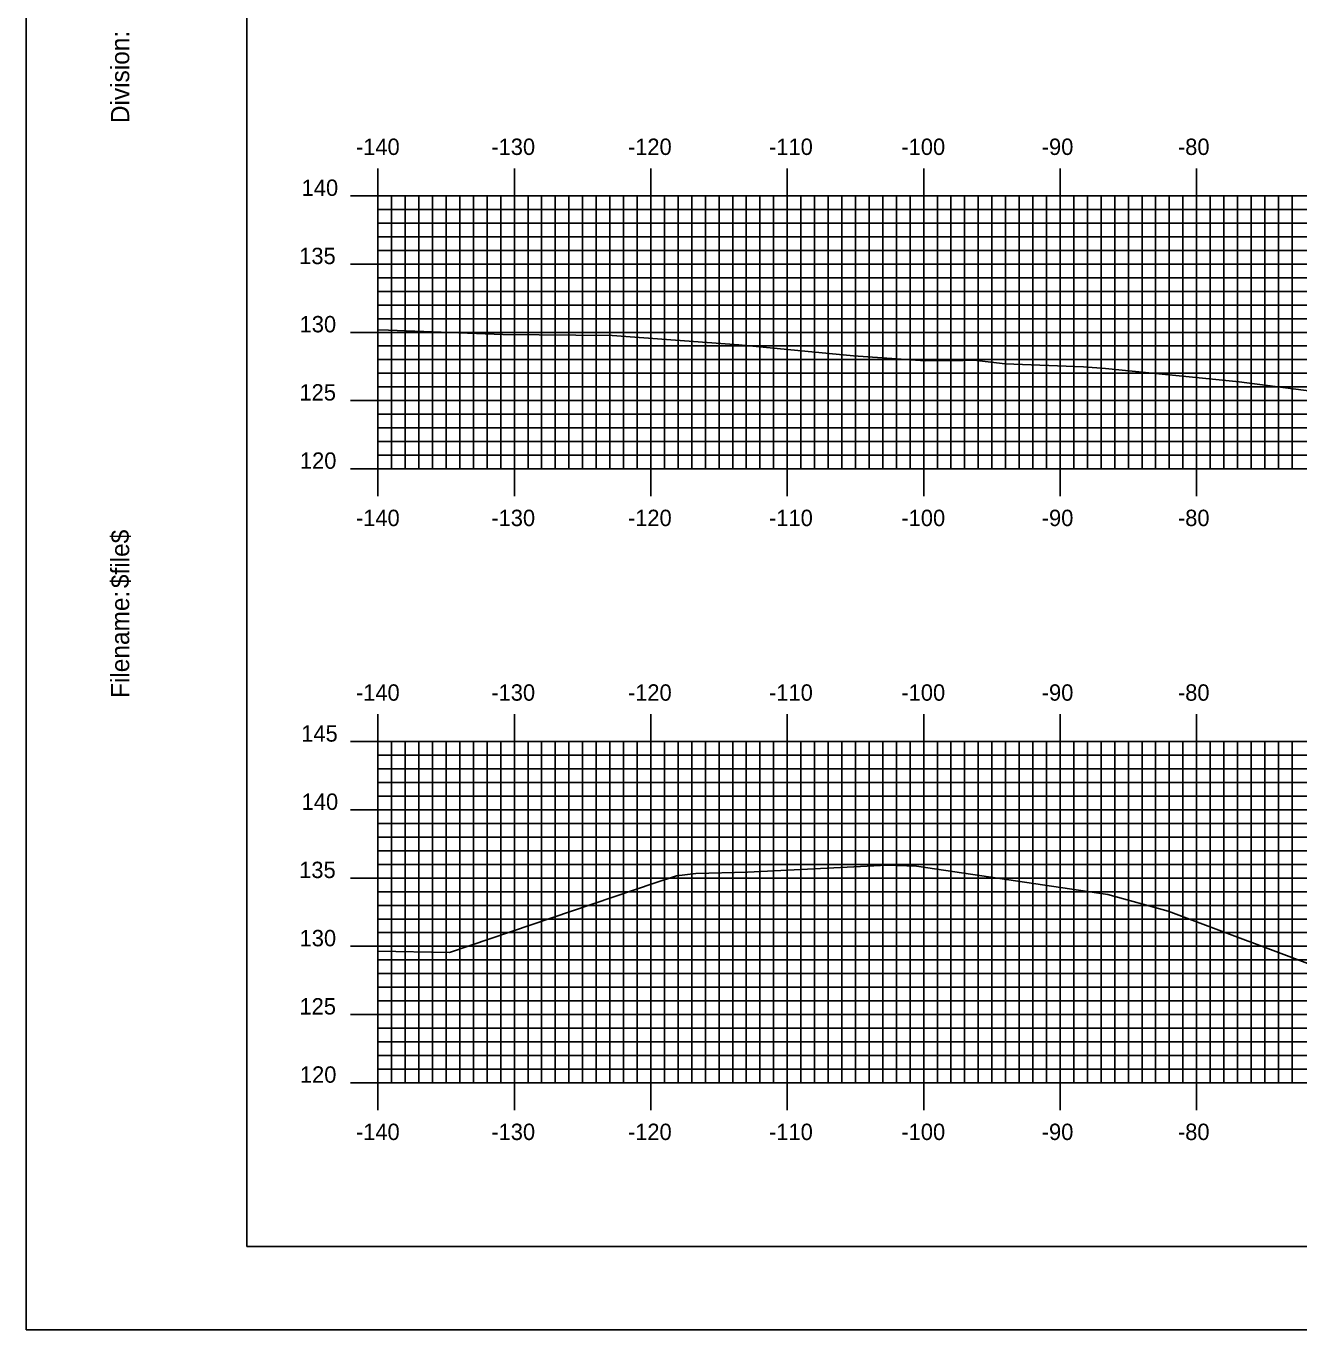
# Model space of a CAD drawing. Extents: x 850746 to 851089, y 366605 to 366825.
# Drawn here: x 850745.6 to 850838.9, y 366604.9 to 366700.5 of the extents above; entities that cross this region are included whole.
import ezdxf

# ---------------------------------------------------------------- set-up
doc = ezdxf.new("R2010")
doc.units = 0
for name, color, linetype in [('BORDER', 7, 'Continuous'), ('H_V ANNOTATION', 7, 'Continuous'), ('MAJOR', 7, 'Continuous'), ('MINOR', 7, 'Continuous'), ('PLOT BOUNDARY', 7, 'Continuous'), ('S_Roadway_Centerline', 7, 'Continuous')]:
    doc.layers.add(name, color=color, linetype=linetype)

msp = doc.modelspace()

# ---------------------------------------------------------------- linework, layer by layer
at = {"layer": 'BORDER'}
msp.add_lwpolyline([(850761.825, 366611.055), (851081.825, 366611.055), (851081.825, 366821.055), (850761.825, 366821.055)], close=True, dxfattribs=at)
at = {"layer": 'MAJOR'}
for p, q in [((850771.425, 366690.059), (850771.425, 366688.055)), ((850781.425, 366690.059), (850781.425, 366688.055)), ((850791.425, 366690.059), (850791.425, 366688.055)), ((850801.425, 366690.059), (850801.425, 366688.055)), ((850811.425, 366690.059), (850811.425, 366688.055)), ((850821.425, 366690.059), (850821.425, 366688.055)), ((850831.425, 366690.059), (850831.425, 366688.055)), ((850769.421, 366688.055), (850771.425, 366688.055)), ((850771.425, 366688.055), (851051.425, 366688.055)), ((850771.425, 366668.055), (850771.425, 366688.055)), ((850771.425, 366668.055), (850771.425, 366688.055)), ((850771.425, 366688.055), (851051.425, 366688.055)), ((850781.425, 366668.055), (850781.425, 366688.055)), ((850791.425, 366668.055), (850791.425, 366688.055)), ((850801.425, 366668.055), (850801.425, 366688.055)), ((850811.425, 366668.055), (850811.425, 366688.055)), ((850821.425, 366668.055), (850821.425, 366688.055)), ((850831.425, 366668.055), (850831.425, 366688.055)), ((850769.421, 366683.055), (850771.425, 366683.055)), ((850771.425, 366683.055), (851051.425, 366683.055)), ((850769.421, 366678.055), (850771.425, 366678.055)), ((850771.425, 366678.055), (851051.425, 366678.055)), ((850769.421, 366673.055), (850771.425, 366673.055)), ((850771.425, 366673.055), (851051.425, 366673.055)), ((850769.421, 366668.055), (850771.425, 366668.055)), ((850771.425, 366668.055), (851051.425, 366668.055)), ((850771.425, 366668.055), (851051.425, 366668.055)), ((850771.425, 366666.051), (850771.425, 366668.055)), ((850781.425, 366666.051), (850781.425, 366668.055)), ((850791.425, 366666.051), (850791.425, 366668.055)), ((850801.425, 366666.051), (850801.425, 366668.055)), ((850811.425, 366666.051), (850811.425, 366668.055)), ((850821.425, 366666.051), (850821.425, 366668.055)), ((850831.425, 366666.051), (850831.425, 366668.055)), ((850771.425, 366650.059), (850771.425, 366648.055)), ((850781.425, 366650.059), (850781.425, 366648.055)), ((850791.425, 366650.059), (850791.425, 366648.055)), ((850801.425, 366650.059), (850801.425, 366648.055)), ((850811.425, 366650.059), (850811.425, 366648.055)), ((850821.425, 366650.059), (850821.425, 366648.055)), ((850831.425, 366650.059), (850831.425, 366648.055)), ((850769.421, 366648.055), (850771.425, 366648.055)), ((850771.425, 366648.055), (851051.425, 366648.055)), ((850771.425, 366623.055), (850771.425, 366648.055)), ((850771.425, 366623.055), (850771.425, 366648.055)), ((850771.425, 366648.055), (851051.425, 366648.055)), ((850781.425, 366623.055), (850781.425, 366648.055)), ((850791.425, 366623.055), (850791.425, 366648.055)), ((850801.425, 366623.055), (850801.425, 366648.055)), ((850811.425, 366623.055), (850811.425, 366648.055)), ((850821.425, 366623.055), (850821.425, 366648.055)), ((850831.425, 366623.055), (850831.425, 366648.055)), ((850769.421, 366643.055), (850771.425, 366643.055)), ((850771.425, 366643.055), (851051.425, 366643.055)), ((850769.421, 366638.055), (850771.425, 366638.055)), ((850771.425, 366638.055), (851051.425, 366638.055)), ((850769.421, 366633.055), (850771.425, 366633.055)), ((850771.425, 366633.055), (851051.425, 366633.055)), ((850769.421, 366628.055), (850771.425, 366628.055)), ((850771.425, 366628.055), (851051.425, 366628.055)), ((850769.421, 366623.055), (850771.425, 366623.055)), ((850771.425, 366623.055), (851051.425, 366623.055)), ((850771.425, 366623.055), (851051.425, 366623.055)), ((850771.425, 366621.051), (850771.425, 366623.055)), ((850781.425, 366621.051), (850781.425, 366623.055)), ((850791.425, 366621.051), (850791.425, 366623.055)), ((850801.425, 366621.051), (850801.425, 366623.055)), ((850811.425, 366621.051), (850811.425, 366623.055)), ((850821.425, 366621.051), (850821.425, 366623.055)), ((850831.425, 366621.051), (850831.425, 366623.055))]:
    msp.add_line(p, q, dxfattribs=at)
at = {"layer": 'MINOR'}
for p, q in [((850772.425, 366668.055), (850772.425, 366688.055)), ((850773.425, 366668.055), (850773.425, 366688.055)), ((850774.425, 366668.055), (850774.425, 366688.055)), ((850775.425, 366668.055), (850775.425, 366688.055)), ((850776.425, 366668.055), (850776.425, 366688.055)), ((850777.425, 366668.055), (850777.425, 366688.055)), ((850778.425, 366668.055), (850778.425, 366688.055)), ((850779.425, 366668.055), (850779.425, 366688.055)), ((850780.425, 366668.055), (850780.425, 366688.055)), ((850782.425, 366668.055), (850782.425, 366688.055)), ((850783.425, 366668.055), (850783.425, 366688.055)), ((850784.425, 366668.055), (850784.425, 366688.055)), ((850785.425, 366668.055), (850785.425, 366688.055)), ((850786.425, 366668.055), (850786.425, 366688.055)), ((850787.425, 366668.055), (850787.425, 366688.055)), ((850788.425, 366668.055), (850788.425, 366688.055)), ((850789.425, 366668.055), (850789.425, 366688.055)), ((850790.425, 366668.055), (850790.425, 366688.055)), ((850792.425, 366668.055), (850792.425, 366688.055)), ((850793.425, 366668.055), (850793.425, 366688.055)), ((850794.425, 366668.055), (850794.425, 366688.055)), ((850795.425, 366668.055), (850795.425, 366688.055)), ((850796.425, 366668.055), (850796.425, 366688.055)), ((850797.425, 366668.055), (850797.425, 366688.055)), ((850798.425, 366668.055), (850798.425, 366688.055)), ((850799.425, 366668.055), (850799.425, 366688.055)), ((850800.425, 366668.055), (850800.425, 366688.055)), ((850802.425, 366668.055), (850802.425, 366688.055)), ((850803.425, 366668.055), (850803.425, 366688.055)), ((850804.425, 366668.055), (850804.425, 366688.055)), ((850805.425, 366668.055), (850805.425, 366688.055)), ((850806.425, 366668.055), (850806.425, 366688.055)), ((850807.425, 366668.055), (850807.425, 366688.055)), ((850808.425, 366668.055), (850808.425, 366688.055)), ((850809.425, 366668.055), (850809.425, 366688.055)), ((850810.425, 366668.055), (850810.425, 366688.055)), ((850812.425, 366668.055), (850812.425, 366688.055)), ((850813.425, 366668.055), (850813.425, 366688.055)), ((850814.425, 366668.055), (850814.425, 366688.055)), ((850815.425, 366668.055), (850815.425, 366688.055)), ((850816.425, 366668.055), (850816.425, 366688.055)), ((850817.425, 366668.055), (850817.425, 366688.055)), ((850818.425, 366668.055), (850818.425, 366688.055)), ((850819.425, 366668.055), (850819.425, 366688.055)), ((850820.425, 366668.055), (850820.425, 366688.055)), ((850822.425, 366668.055), (850822.425, 366688.055)), ((850823.425, 366668.055), (850823.425, 366688.055)), ((850824.425, 366668.055), (850824.425, 366688.055)), ((850825.425, 366668.055), (850825.425, 366688.055)), ((850826.425, 366668.055), (850826.425, 366688.055)), ((850827.425, 366668.055), (850827.425, 366688.055)), ((850828.425, 366668.055), (850828.425, 366688.055)), ((850829.425, 366668.055), (850829.425, 366688.055)), ((850830.425, 366668.055), (850830.425, 366688.055)), ((850832.425, 366668.055), (850832.425, 366688.055)), ((850833.425, 366668.055), (850833.425, 366688.055)), ((850834.425, 366668.055), (850834.425, 366688.055)), ((850835.425, 366668.055), (850835.425, 366688.055)), ((850836.425, 366668.055), (850836.425, 366688.055)), ((850837.425, 366668.055), (850837.425, 366688.055)), ((850838.425, 366668.055), (850838.425, 366688.055)), ((850771.425, 366687.055), (851051.425, 366687.055)), ((850771.425, 366687.055), (850773.429, 366687.055)), ((850771.425, 366686.055), (851051.425, 366686.055)), ((850771.425, 366686.055), (850773.429, 366686.055)), ((850771.425, 366685.055), (851051.425, 366685.055)), ((850771.425, 366685.055), (850773.429, 366685.055)), ((850771.425, 366684.055), (851051.425, 366684.055)), ((850771.425, 366684.055), (850773.429, 366684.055)), ((850771.425, 366682.055), (851051.425, 366682.055)), ((850771.425, 366682.055), (850773.429, 366682.055)), ((850771.425, 366681.055), (851051.425, 366681.055)), ((850771.425, 366681.055), (850773.429, 366681.055)), ((850771.425, 366680.055), (851051.425, 366680.055)), ((850771.425, 366680.055), (850773.429, 366680.055)), ((850771.425, 366679.055), (851051.425, 366679.055)), ((850771.425, 366679.055), (850773.429, 366679.055)), ((850771.425, 366677.055), (851051.425, 366677.055)), ((850771.425, 366677.055), (850773.429, 366677.055)), ((850771.425, 366676.055), (851051.425, 366676.055)), ((850771.425, 366676.055), (850773.429, 366676.055)), ((850771.425, 366675.055), (851051.425, 366675.055)), ((850771.425, 366675.055), (850773.429, 366675.055)), ((850771.425, 366674.055), (851051.425, 366674.055)), ((850771.425, 366674.055), (850773.429, 366674.055)), ((850771.425, 366672.055), (851051.425, 366672.055)), ((850771.425, 366672.055), (850773.429, 366672.055)), ((850771.425, 366671.055), (851051.425, 366671.055)), ((850771.425, 366671.055), (850773.429, 366671.055)), ((850771.425, 366670.055), (851051.425, 366670.055)), ((850771.425, 366670.055), (850773.429, 366670.055)), ((850771.425, 366669.055), (851051.425, 366669.055)), ((850771.425, 366669.055), (850773.429, 366669.055)), ((850772.425, 366623.055), (850772.425, 366648.055)), ((850773.425, 366623.055), (850773.425, 366648.055)), ((850774.425, 366623.055), (850774.425, 366648.055)), ((850775.425, 366623.055), (850775.425, 366648.055)), ((850776.425, 366623.055), (850776.425, 366648.055)), ((850777.425, 366623.055), (850777.425, 366648.055)), ((850778.425, 366623.055), (850778.425, 366648.055)), ((850779.425, 366623.055), (850779.425, 366648.055)), ((850780.425, 366623.055), (850780.425, 366648.055)), ((850782.425, 366623.055), (850782.425, 366648.055)), ((850783.425, 366623.055), (850783.425, 366648.055)), ((850784.425, 366623.055), (850784.425, 366648.055)), ((850785.425, 366623.055), (850785.425, 366648.055)), ((850786.425, 366623.055), (850786.425, 366648.055)), ((850787.425, 366623.055), (850787.425, 366648.055)), ((850788.425, 366623.055), (850788.425, 366648.055)), ((850789.425, 366623.055), (850789.425, 366648.055)), ((850790.425, 366623.055), (850790.425, 366648.055)), ((850792.425, 366623.055), (850792.425, 366648.055)), ((850793.425, 366623.055), (850793.425, 366648.055)), ((850794.425, 366623.055), (850794.425, 366648.055)), ((850795.425, 366623.055), (850795.425, 366648.055)), ((850796.425, 366623.055), (850796.425, 366648.055)), ((850797.425, 366623.055), (850797.425, 366648.055)), ((850798.425, 366623.055), (850798.425, 366648.055)), ((850799.425, 366623.055), (850799.425, 366648.055)), ((850800.425, 366623.055), (850800.425, 366648.055)), ((850802.425, 366623.055), (850802.425, 366648.055)), ((850803.425, 366623.055), (850803.425, 366648.055)), ((850804.425, 366623.055), (850804.425, 366648.055)), ((850805.425, 366623.055), (850805.425, 366648.055)), ((850806.425, 366623.055), (850806.425, 366648.055)), ((850807.425, 366623.055), (850807.425, 366648.055)), ((850808.425, 366623.055), (850808.425, 366648.055)), ((850809.425, 366623.055), (850809.425, 366648.055)), ((850810.425, 366623.055), (850810.425, 366648.055)), ((850812.425, 366623.055), (850812.425, 366648.055)), ((850813.425, 366623.055), (850813.425, 366648.055)), ((850814.425, 366623.055), (850814.425, 366648.055)), ((850815.425, 366623.055), (850815.425, 366648.055)), ((850816.425, 366623.055), (850816.425, 366648.055)), ((850817.425, 366623.055), (850817.425, 366648.055)), ((850818.425, 366623.055), (850818.425, 366648.055)), ((850819.425, 366623.055), (850819.425, 366648.055)), ((850820.425, 366623.055), (850820.425, 366648.055)), ((850822.425, 366623.055), (850822.425, 366648.055)), ((850823.425, 366623.055), (850823.425, 366648.055)), ((850824.425, 366623.055), (850824.425, 366648.055)), ((850825.425, 366623.055), (850825.425, 366648.055)), ((850826.425, 366623.055), (850826.425, 366648.055)), ((850827.425, 366623.055), (850827.425, 366648.055)), ((850828.425, 366623.055), (850828.425, 366648.055)), ((850829.425, 366623.055), (850829.425, 366648.055)), ((850830.425, 366623.055), (850830.425, 366648.055)), ((850832.425, 366623.055), (850832.425, 366648.055)), ((850833.425, 366623.055), (850833.425, 366648.055)), ((850834.425, 366623.055), (850834.425, 366648.055)), ((850835.425, 366623.055), (850835.425, 366648.055)), ((850836.425, 366623.055), (850836.425, 366648.055)), ((850837.425, 366623.055), (850837.425, 366648.055)), ((850838.425, 366623.055), (850838.425, 366648.055)), ((850771.425, 366647.055), (851051.425, 366647.055)), ((850771.425, 366647.055), (850773.429, 366647.055)), ((850771.425, 366646.055), (851051.425, 366646.055)), ((850771.425, 366646.055), (850773.429, 366646.055)), ((850771.425, 366645.055), (851051.425, 366645.055)), ((850771.425, 366645.055), (850773.429, 366645.055)), ((850771.425, 366644.055), (851051.425, 366644.055)), ((850771.425, 366644.055), (850773.429, 366644.055)), ((850771.425, 366642.055), (851051.425, 366642.055)), ((850771.425, 366642.055), (850773.429, 366642.055)), ((850771.425, 366641.055), (851051.425, 366641.055)), ((850771.425, 366641.055), (850773.429, 366641.055)), ((850771.425, 366640.055), (851051.425, 366640.055)), ((850771.425, 366640.055), (850773.429, 366640.055)), ((850771.425, 366639.055), (851051.425, 366639.055)), ((850771.425, 366639.055), (850773.429, 366639.055)), ((850771.425, 366637.055), (851051.425, 366637.055)), ((850771.425, 366637.055), (850773.429, 366637.055)), ((850771.425, 366636.055), (851051.425, 366636.055)), ((850771.425, 366636.055), (850773.429, 366636.055)), ((850771.425, 366635.055), (851051.425, 366635.055)), ((850771.425, 366635.055), (850773.429, 366635.055)), ((850771.425, 366634.055), (851051.425, 366634.055)), ((850771.425, 366634.055), (850773.429, 366634.055)), ((850771.425, 366632.055), (851051.425, 366632.055)), ((850771.425, 366632.055), (850773.429, 366632.055)), ((850771.425, 366631.055), (851051.425, 366631.055)), ((850771.425, 366631.055), (850773.429, 366631.055)), ((850771.425, 366630.055), (851051.425, 366630.055)), ((850771.425, 366630.055), (850773.429, 366630.055)), ((850771.425, 366629.055), (851051.425, 366629.055)), ((850771.425, 366629.055), (850773.429, 366629.055)), ((850771.425, 366627.055), (851051.425, 366627.055)), ((850771.425, 366627.055), (850773.429, 366627.055)), ((850771.425, 366626.055), (851051.425, 366626.055)), ((850771.425, 366626.055), (850773.429, 366626.055)), ((850771.425, 366625.055), (851051.425, 366625.055)), ((850771.425, 366625.055), (850773.429, 366625.055)), ((850771.425, 366624.055), (851051.425, 366624.055)), ((850771.425, 366624.055), (850773.429, 366624.055))]:
    msp.add_line(p, q, dxfattribs=at)
at = {"layer": 'PLOT BOUNDARY'}
msp.add_lwpolyline([(850745.639, 366604.937), (851085.639, 366604.937), (851085.639, 366824.937), (850745.639, 366824.937)], close=True, dxfattribs=at)
at = {"layer": 'S_Roadway_Centerline'}
for points in [[(850771.425, 366678.23), (850772.196, 366678.217), (850780.578, 366677.907), (850788.6, 366677.817), (850797.888, 366677.15), (850806.284, 366676.333), (850811.54, 366675.978), (850814.287, 366675.983), (850815.1, 366676.009), (850817.404, 366675.748), (850823.144, 366675.529), (850824.74, 366675.404), (850834.55, 366674.417), (850840.022, 366673.714)], [(850771.425, 366632.692), (850776.674, 366632.598), (850791.753, 366637.714), (850793.306, 366638.223), (850794.733, 366638.383), (850798.515, 366638.481), (850808.742, 366638.997), (850810.905, 366638.929), (850824.926, 366636.842), (850829.346, 366635.618), (850841.149, 366631.205)]]:
    msp.add_lwpolyline(points, dxfattribs=at)

# ---------------------------------------------------------------- texts
at = {"layer": 'BORDER'}
for s, p in [('Division:', (850753.195, 366693.387)), ('$file$', (850753.195, 366659.306)), ('Filename:', (850753.195, 366651.252))]:
    msp.add_text(s, height=1.3392, rotation=90, dxfattribs=at).set_placement(p)
at = {"layer": 'H_V ANNOTATION'}
for s, p in [('-140', (850769.809, 366691.055)), ('-130', (850779.734, 366691.055)), ('-120', (850789.745, 366691.055)), ('-110', (850800.088, 366691.055)), ('-100', (850809.788, 366691.055)), ('-90', (850820.077, 366691.055)), ('-80', (850830.055, 366691.055)), ('140', (850765.835, 366688.055)), ('135', (850765.653, 366683.055)), ('130', (850765.685, 366678.055)), ('125', (850765.674, 366673.055)), ('120', (850765.706, 366668.055)), ('-140', (850769.809, 366663.855)), ('-130', (850779.734, 366663.855)), ('-120', (850789.745, 366663.855)), ('-110', (850800.088, 366663.855)), ('-100', (850809.788, 366663.855)), ('-90', (850820.077, 366663.855)), ('-80', (850830.055, 366663.855)), ('-140', (850769.809, 366651.055)), ('-130', (850779.734, 366651.055)), ('-120', (850789.745, 366651.055)), ('-110', (850800.088, 366651.055)), ('-100', (850809.788, 366651.055)), ('-90', (850820.077, 366651.055)), ('-80', (850830.055, 366651.055)), ('145', (850765.803, 366648.055)), ('140', (850765.835, 366643.055)), ('135', (850765.653, 366638.055)), ('130', (850765.685, 366633.055)), ('125', (850765.674, 366628.055)), ('120', (850765.706, 366623.055)), ('-140', (850769.809, 366618.855)), ('-130', (850779.734, 366618.855)), ('-120', (850789.745, 366618.855)), ('-110', (850800.088, 366618.855)), ('-100', (850809.788, 366618.855)), ('-90', (850820.077, 366618.855)), ('-80', (850830.055, 366618.855))]:
    msp.add_text(s, height=1.2, dxfattribs=at).set_placement(p)
at = {"layer": 'MAJOR'}
for p in [(850771.416, 366668.055), (850771.416, 366623.055)]:
    msp.add_text('-', height=0.012, dxfattribs=at).set_placement(p)

doc.saveas('drawing.dxf')
